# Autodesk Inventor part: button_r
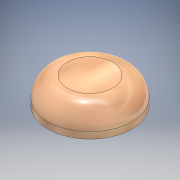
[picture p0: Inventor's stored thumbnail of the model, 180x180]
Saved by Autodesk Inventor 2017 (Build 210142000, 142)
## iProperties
Created: 2017-05
Part Number: button_r
Material: Generic
Document SubType Name: Modeling
Designer: alez_
Density: 1 g/cm^3
Appearance: Default
Author: alez_
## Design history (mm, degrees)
derived "button.ipt" dims "d0" = 11
feature "Solid1::button.ipt" dims "d0" = 11
tag "TaggingFeature1"
body "Solid1"
